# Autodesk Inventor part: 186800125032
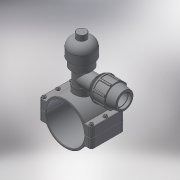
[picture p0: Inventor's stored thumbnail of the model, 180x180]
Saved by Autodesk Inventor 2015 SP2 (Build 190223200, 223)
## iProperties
Created: 2017-05
Part Number: 186800125032
Material: Generic
Description: PLASSON MECHANICAL TAPPING VALVE 125-32
Document SubType Name: Modeling
Designer: KIM
Density: 1 g/cm^3
Appearance: Default
Author: KIM
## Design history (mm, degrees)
derived "18680.ipt"
feature "Solid1::18680.ipt"
feature "Solid2::18680.ipt"
tag "TaggingFeature1"
body "Solid1"
other parameters: "d0" = 137.5, "d1" = 184, "d2" = 62.5, "d3" = 125, "d4" = 124, "d5" = 0, "d6" = 9.2, "d7" = 184, "d8" = 0.1, "d10" = 0, "d11" = 1.25, "d14" = 50.6376, "d20" = 1.25, "d23" = 1.25, "d36" = 13, "d37" = 10.4, "d38" = 70.5, "d39" = 0, "d40" = 3, "d41" = 5, "d42" = 0, "d43" = 8, "d44" = 3, "d45" = 0, "d46" = 1.25, "d51" = 98, "d52" = 38.952, "d53" = 25, "d54" = 0, "d55" = 32, "d57" = 0, "d58" = 135, "d60" = 0, "d62" = 13, "d63" = 10.4, "d66" = 103.2, "d67" = 32, "d68" = 11.25, "d69" = 27, "d70" = 64, "d71" = 48, "d72" = 1.92857, "d73" = 51.2, "d74" = 120 deg, "d75" = 48, "d76" = 10 deg, "d77" = 57.6, "d78" = 40.5, "d79" = 67, "d80" = 25.6, "d81" = 135, "d82" = 6.7, "d87" = 19.28571, "d90" = 59.52, "d91" = 35 deg, "d92" = 17.5 deg, "d94" = 0, "d96" = 360 deg, "d98" = 0.64, "d99" = 73.7, "d100" = 38.4, "d101" = 135 deg, "d102" = 1.28, "d105" = 3.2, "d106" = 0, "d107" = 0.1, "d109" = 50.6376, "d112" = 34.85714, "d113" = 4.5, "d116" = 0, "d121" = 46.7424, "d122" = 77.904, "d123" = 66.2184, "d124" = 45 deg, "d125" = 219.6, "d126" = 244, "d127" = 146.4, "d128" = 1, "d_" = 125, "B_" = 32, "G_" = 38.952, "A_" = 98, "L_" = 184, "L_1" = 124, "l_2" = 25, "d_1" = 32, "E_" = 64, "l_" = 67, "H_" = 135, "H_2" = 244
